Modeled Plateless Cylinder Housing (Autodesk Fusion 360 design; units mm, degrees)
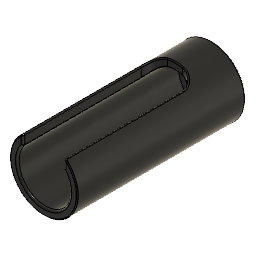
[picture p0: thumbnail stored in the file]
sketch "Sketch1" plane through (0, 0, 0) normal (1, 0, 0) x axis (0, 1, 0)
  line L1 (104.14, 17.78) -> (0, 17.78)
  line L2 (0, 17.78) -> (0, 22.86)
  line L3 (114.3, 22.86) -> (0, 22.86)
  line L4 (0, 0) -> (114.3, 0)
  line L5 (114.3, 17.78) -> (104.14, 17.78)
  line L6 (114.3, 22.86) -> (114.3, 17.78)
  line L7 (114.3, 8.7313) -> (114.3, 17.78)
  line L8 (109.22, 8.7313) -> (114.3, 8.7313)
  line L9 (109.22, 17.78) -> (109.22, 8.7313)
  point P5 (114.3, 0)
  point P6 (114.3, 22.86)
  point P3 (0, 17.78)
  point P4 (104.14, 17.78)
  point P2 (0, 22.86)
  point P1 (0, 0)
  point P7 (0, 0)
  point P11 (109.22, 17.78)
  point P9 (114.3, 8.7313)
  point P10 (109.22, 8.7313)
  vertical P5 P6
  horizontal P3 P4
  vertical P2 P3
  vertical P1 P3
  horizontal P2 P6
  coincident P1 P7
  parallel L1 L5
  perpendicular L3 L6
  perpendicular L5 L7
  perpendicular L6 L8
  coincident L5 P11
  perpendicular L5 L9
  dimension "d1" distance P2 P6 = 114.3
  dimension "d3" distance P1 L1 = 17.78
  dimension "d14" distance L1 L3 = 5.08
  dimension "d110" = 17.4625
  dimension "d113" distance P9 P10 = 5.08
revolve "Revolve1" sketch "Sketch1" AlongAngle 360
sketch "Sketch3" plane through (0, 0, 0) normal (0, 0, 1) x axis (1, 0, 0)
  line L1 (13.97, 0) -> (-13.97, 0)
  line L2 (13.97, 88.9) -> (13.97, 0)
  line L3 (-13.97, 88.9) -> (13.97, 88.9)
  line L4 (-13.97, 0) -> (-13.97, 88.9)
  point P1 (0, 0)
  point P2 (-13.97, 0)
  point P3 (13.97, 0)
  point P5 (-13.97, 88.9)
  horizontal L1
  vertical L2
  horizontal L3
  vertical L4
  coincident P1 L1
  midpoint P1 L1
  dimension "d7" distance P2 P3 = 27.94
  dimension "d8" distance P2 P5 = 88.9
extrude "Extrude1" cut sketch "Sketch3" along normal blind 30.48
chamfer "Chamfer2" distance 0.508
fillet "Fillet1" radius 8.89
sketch "Sketch4" plane through (0, 114.3, 0) normal (0, 1, 0) x axis (-1, 0, 0)
  line L1 (5.5825, -29.1664) -> (2.8706, -33.9505)
  line L2 (2.7953, -24.4258) -> (5.5825, -29.1664)
  line L3 (-2.7038, -24.4693) -> (2.7953, -24.4258)
  line L4 (-5.4157, -29.2534) -> (-2.7038, -24.4693)
  line L5 (-2.6284, -33.994) -> (-5.4157, -29.2534)
  line L6 (2.8706, -33.9505) -> (-2.6284, -33.994)
  line L7 (28.042, 9.9366) -> (22.5429, 9.8931)
  line L8 (30.7539, 14.7207) -> (28.042, 9.9366)
  line L9 (27.9667, 19.4613) -> (30.7539, 14.7207)
  line L10 (22.4676, 19.4178) -> (27.9667, 19.4613)
  line L11 (19.7557, 14.6337) -> (22.4676, 19.4178)
  line L12 (22.5429, 9.8931) -> (19.7557, 14.6337)
  line L13 (-22.6263, 19.3168) -> (-19.8391, 14.5762)
  line L14 (-28.1254, 19.2733) -> (-22.6263, 19.3168)
  line L15 (-30.8373, 14.4892) -> (-28.1254, 19.2733)
  line L16 (-28.0501, 9.7486) -> (-30.8373, 14.4892)
  line L17 (-22.551, 9.7921) -> (-28.0501, 9.7486)
  line L18 (-19.8391, 14.5762) -> (-22.551, 9.7921)
  line L19 (-5.4715, -22.1955) -> (-5.4157, -29.2534)
  line L20 (5.5272, -22.1817) -> (5.5825, -29.1664)
  line L21 (21.9577, 6.3593) -> (28.042, 9.9366)
  line L22 (16.4463, 15.8776) -> (22.4676, 19.4178)
  line L23 (-16.4862, 15.8362) -> (-22.6263, 19.3168)
  line L24 (-21.9736, 6.3041) -> (-28.0501, 9.7486)
  circle C1 centre (0, 0) radius 22.86
  circle C2 centre (0, 0) radius 12.7
  circle C3 centre (0.0834, -29.2099) radius 2.4765
  circle C4 centre (25.2548, 14.6772) radius 2.4765
  circle C5 centre (-25.3382, 14.5327) radius 2.4765
  circle C6 centre (0.0834, -29.2099) radius 5.4993
  circle C7 centre (25.2548, 14.6772) radius 5.4993
  circle C8 centre (-25.3382, 14.5327) radius 5.4993
  circle C9 centre (0, 0) radius 22.86
  circle C10 centre (0, 0) radius 22.86
  circle C11 centre (0, 0) radius 8.7313
  point P1 (0, 0)
  point P3 (0, 0)
  point P4 (0.0834, -29.2099)
  point P13 (0.0834, -29.2099)
  point P7 (2.8706, -33.9505)
  point P30 (0, 0)
  point P31 (-5.4715, -22.1955)
  point P32 (5.5272, -22.1817)
  coincident P1 P3
  coincident P4 P13
  concentric C3 C6
  coincident P7 C6
  coincident P3 P30
  coincident C1 P31
  tangent C6 L19
  coincident C9 P32
  tangent C6 L20
  parallel L19 L20
  dimension "d17" diameter C3 = 4.953
  dimension "d18" distance P3 P4 = 29.21
  dimension "d24" distance L3 L6 = 9.525
  dimension "d20" C-Pattern1-Angle = 360
  dimension "d26" C-Pattern2-Angle = 360
  dimension "d97" C-Pattern3-Angle = 360
fillet "Fillet20" radius 1.27
fillet "Fillet23" radius 0.635 0.635
fillet "Fillet24" radius 1.27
